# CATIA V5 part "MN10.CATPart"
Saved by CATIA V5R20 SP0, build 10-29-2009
Part number: MN10
Definition: NONE
Nomenclature: MN10
Source: Unknown
Description: MN10
Bounding box of the stored display mesh (mm): x 0 to 12, y -5 to 5, z -5 to 5
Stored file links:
  C:\Users\Utente\Desktop\IO LAVORO\3D X SITO CF\X SITO\PLASTICA\CFMR\MN10.CATPart
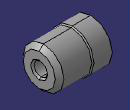
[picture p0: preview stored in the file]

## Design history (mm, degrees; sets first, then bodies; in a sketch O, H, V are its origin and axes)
Body1 "MN10" (main body)
  Solid1: solid without history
